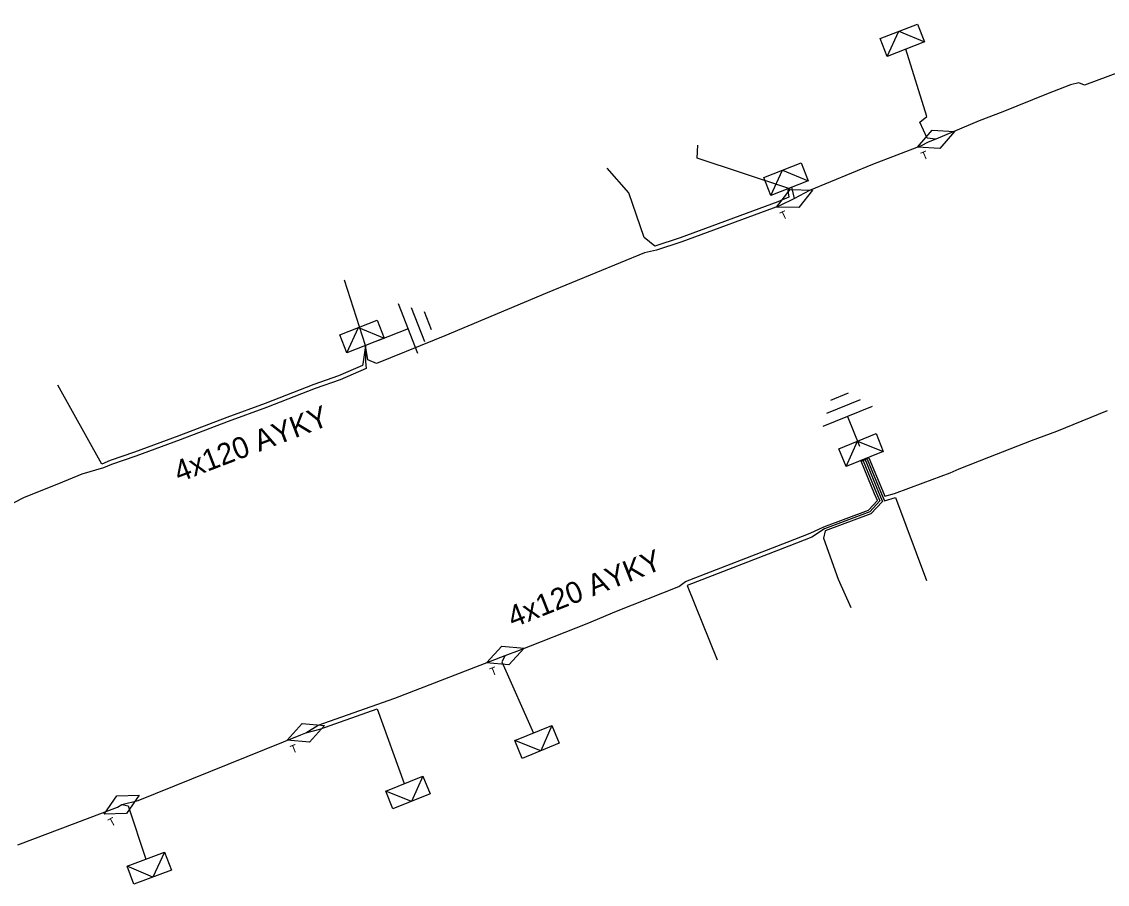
# Model space of a CAD drawing. Extents: x -540028 to -538776, y -1157064 to -1155670.
# Drawn here: x -539834.1 to -539783.3, y -1155860.4 to -1155820 of the extents above; entities that cross this region are included whole.
import ezdxf

# ---------------------------------------------------------------- set-up
doc = ezdxf.new("R2010")
doc.units = 0
for name, color, linetype in [('Vrstva 15', 7, 'Continuous'), ('Vrstva 19', 7, 'Continuous'), ('Vrstva 2', 7, 'Continuous'), ('Vrstva 31', 7, 'Continuous'), ('Vrstva 5', 7, 'Continuous'), ('Vrstva 52', 7, 'Continuous'), ('Vrstva 6', 7, 'Continuous')]:
    doc.layers.add(name, color=color, linetype=linetype)

# ---------------------------------------------------------------- blocks, each defined once
blk = doc.blocks.new('17.1')
at = {"layer": 'Vrstva 2'}
blk.add_lwpolyline([(-1.875, 0), (0, 0.9375), (1.875, 0), (0, -0.9375)], close=True, dxfattribs=at)
blk.add_text('T', height=0.75, dxfattribs=at).set_placement((-1.875, -1.35))
blk = doc.blocks.new('23')
at = {"layer": 'Vrstva 2'}
blk.add_lwpolyline([(1.875, -1.8), (-1.875, -1.8), (-1.875, 0), (1.875, 0)], close=True, dxfattribs=at)
blk.add_lwpolyline([(1.875, 0), (0, -1.8), (-1.875, 0)], dxfattribs=at)
blk = doc.blocks.new('11')
at = {"layer": 'Vrstva 2'}
for p, q in [((0, -4.3), (0, -1.3)), ((-2.5, -4.3), (2.5, -4.3)), ((-1.7, -5.3), (1.7, -5.3)), ((-0.9, -6.3), (0.9, -6.3))]:
    blk.add_line(p, q, dxfattribs=at)

msp = doc.modelspace()

# ---------------------------------------------------------------- linework, layer by layer
at = {"layer": 'Vrstva 5'}
for points in [[(-539777.218, -1155819.97), (-539780.574, -1155821.321), (-539780.94, -1155821.68), (-539784.34, -1155822.95), (-539784.6, -1155822.83), (-539785, -1155822.93), (-539786.12, -1155823.37), (-539788.17, -1155824.19), (-539789.28, -1155824.62), (-539791.3, -1155825.48), (-539791.66, -1155825.62), (-539792, -1155825.78), (-539794.27, -1155826.66), (-539797.23, -1155827.88), (-539797.924, -1155828.259)], [(-539797.924, -1155828.259), (-539798.055, -1155827.728), (-539798.159, -1155827.769)], [(-539797.924, -1155828.26), (-539798.633, -1155828.593), (-539803.207, -1155830.284), (-539804.395, -1155830.674), (-539804.95, -1155830.8), (-539809.51, -1155832.67), (-539814.31, -1155834.69), (-539814.8, -1155834.9), (-539817.51, -1155835.99), (-539817.918, -1155835.822), (-539818.02, -1155835.141), (-539818.025, -1155835.901), (-539817.993, -1155836.221), (-539819.203, -1155836.753), (-539820.375, -1155837.164), (-539822.655, -1155838.054), (-539824.445, -1155838.704), (-539826.695, -1155839.564), (-539828.777, -1155840.324), (-539829.913, -1155840.713), (-539830.291, -1155840.882), (-539831.31, -1155841.17), (-539832.4, -1155841.62), (-539834, -1155842.27), (-539835.04, -1155842.79)], [(-539834.3, -1155858.55), (-539829.64, -1155856.77), (-539829.44, -1155856.66), (-539828.67, -1155856.47), (-539821.05, -1155853.39), (-539820.82, -1155853.3), (-539820.238, -1155852.937), (-539816.65, -1155851.67), (-539811.47, -1155849.67), (-539810.81, -1155849.42), (-539807.64, -1155848.17), (-539806.26, -1155847.59), (-539803.34, -1155846.43), (-539803.026, -1155846.207), (-539798.266, -1155844.357), (-539797.189, -1155843.938), (-539796.555, -1155843.646), (-539794.457, -1155842.855), (-539794.042, -1155842.409), (-539794.176, -1155842.095), (-539794.808, -1155840.557), (-539794.632, -1155840.46), (-539794.438, -1155840.407), (-539793.804, -1155841.945), (-539793.696, -1155842.202), (-539793.247, -1155842.074), (-539791.9, -1155841.58), (-539790.63, -1155841.11), (-539790.22, -1155840.93), (-539788.82, -1155840.38), (-539786.83, -1155839.6), (-539785.64, -1155839.16), (-539783.26, -1155838.19)]]:
    msp.add_lwpolyline(points, dxfattribs=at)
at = {"layer": 'Vrstva 52'}
for points in [[(-539791.3, -1155825.48), (-539791.71, -1155825.43), (-539792.05, -1155824.68), (-539791.72, -1155824.42), (-539792.711, -1155821.257)], [(-539798.159, -1155827.769), (-539798.198, -1155827.784), (-539802.48, -1155826.36), (-539802.455, -1155825.753)], [(-539798.159, -1155827.769), (-539798.242, -1155827.882), (-539798.198, -1155828.188), (-539798.707, -1155828.407), (-539803.273, -1155830.096), (-539804.465, -1155830.486), (-539804.97, -1155830.08), (-539805.69, -1155827.99), (-539806.7, -1155826.835)], [(-539818.02, -1155835.141), (-539819.01, -1155832.075)], [(-539818.02, -1155835.141), (-539818.13, -1155835.914), (-539818.167, -1155836.079), (-539819.277, -1155836.567), (-539820.445, -1155836.976), (-539822.725, -1155837.866), (-539824.515, -1155838.516), (-539826.765, -1155839.376), (-539828.843, -1155840.136), (-539829.987, -1155840.527), (-539830.369, -1155840.698), (-539832.432, -1155837.008)], [(-539794.632, -1155840.46), (-539794.707, -1155840.541), (-539794.083, -1155842.057), (-539793.925, -1155842.43), (-539794.4, -1155842.94), (-539796.52, -1155843.74), (-539797.111, -1155844.122), (-539798.194, -1155844.543), (-539802.954, -1155846.393), (-539801.543, -1155849.881)], [(-539794.632, -1155840.46), (-539793.99, -1155842.02), (-539793.807, -1155842.451), (-539794.343, -1155843.025), (-539796.485, -1155843.834), (-539796.57, -1155844.17), (-539795.88, -1155846.1), (-539795.29, -1155847.417)], [(-539794.632, -1155840.46), (-539794.522, -1155840.465), (-539793.897, -1155841.983), (-539793.714, -1155842.415), (-539793.193, -1155842.266), (-539791.737, -1155846.163)], [(-539811.47, -1155849.67), (-539811.63, -1155849.97), (-539810.154, -1155853.303)], [(-539820.82, -1155853.3), (-539820.162, -1155853.123), (-539817.48, -1155852.175), (-539816.201, -1155855.673)], [(-539829.44, -1155856.66), (-539829.13, -1155856.72), (-539828.306, -1155859.22)]]:
    msp.add_lwpolyline(points, dxfattribs=at)

# ---------------------------------------------------------------- block references
at = {"layer": 'Vrstva 15', "xscale": 0.49999999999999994, "yscale": 0.5000000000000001}
for p, rotation in [((-539818.019, -1155835.141), 111.38205273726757), ((-539794.632, -1155840.46), -157.69379442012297)]:
    msp.add_blockref('11', p, dxfattribs=dict(at, rotation=rotation))
at = {"layer": 'Vrstva 19'}
for p, xscale, yscale, rotation in [((-539791.3, -1155825.48), 0.5, 0.5, 23.061519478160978), ((-539797.924, -1155828.259), 0.5, 0.5, 25.18000557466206), ((-539811.47, -1155849.67), 0.5, 0.5000000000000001, 21.111594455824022), ((-539820.82, -1155853.3), 0.5, 0.5000000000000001, 21.370622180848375), ((-539829.44, -1155856.66), 0.49999999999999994, 0.5000000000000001, 28.81079439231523)]:
    msp.add_blockref('17.1', p, dxfattribs=dict(at, xscale=xscale, yscale=yscale, rotation=rotation))
at = {"layer": 'Vrstva 31'}
for p, xscale, yscale, rotation in [((-539792.71, -1155821.256), 0.5, 0.5000000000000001, -158.80439440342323), ((-539798.159, -1155827.769), 0.49999999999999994, 0.5000000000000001, -158.33885000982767), ((-539818.019, -1155835.141), 0.5000000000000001, 0.5, -158.61794714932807), ((-539794.632, -1155840.46), 0.5, 0.49999999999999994, -157.69379454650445), ((-539810.153, -1155853.302), 0.49999999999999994, 0.5000000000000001, 22.35716116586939), ((-539816.201, -1155855.672), 0.5, 0.5, 21.938752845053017), ((-539828.305, -1155859.219), 0.5, 0.5000000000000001, 20.667688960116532)]:
    msp.add_blockref('23', p, dxfattribs=dict(at, xscale=xscale, yscale=yscale, rotation=rotation))

# ---------------------------------------------------------------- texts
at = {"layer": 'Vrstva 6'}
for rotation, p in [(20.918, (-539826.753, -1155841.566)), (21.52, (-539811.115, -1155848.38))]:
    msp.add_text('4x120 AYKY', height=1, rotation=rotation, dxfattribs=at).set_placement(p)

doc.saveas('drawing.dxf')
